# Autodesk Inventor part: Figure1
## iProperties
Created: 2002-04
Part Number: Figure1
Document SubType Name: Modeling
Density: 1 g/cm^3
Control State: 0
Master: False
Checked Out: False
Shininess: 77.0
Angle Display Precision: 2
Document Length Units: 11269
Document Angle Units: 11279
Document Time Units: 11290
Document Mass Units: 11283
Document Length Units Precision: 3
Document Angle Units Precision: 2
Compacted: True
Density: 0.0
Volumn: 0.0
Area: 0.0
PropertySet Name: Model Information
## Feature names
1. Sweep1
2. Shell1
